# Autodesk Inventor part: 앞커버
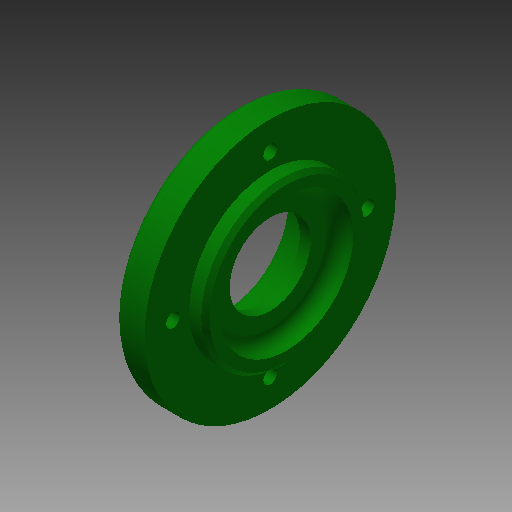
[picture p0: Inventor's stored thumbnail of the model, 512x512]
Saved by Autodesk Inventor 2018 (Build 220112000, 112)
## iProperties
Created: 2015-09
Part Number: 앞커버
Material: 알루미늄 6061
Document SubType Name: Modeling
Designer: mduedu
Density: 2.71 g/cm^3
Mass: 58.9874 g
Surface Area: 98.7754 cm^2
Volume: 21.7666 cm^3
Appearance: 진녹색
Author: mduedu
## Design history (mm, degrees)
sketch "스케치1"
  geometry: L1 (-8, 67)-(-12, 67); L2 (-12, 67)-(-12, 78); L3 (-12, 78)-(-20, 78); L4 (-20, 78)-(-20, 66); L5 (-23, 66)-(-23, 57); L6 (-23, 57)-(-8, 57); L7 (-8, 57)-(-8, 67); L8 (-79.5, 39.5)-(-79.5, 54.5) reference; L9 (48.5, 54.5)-(48.5, 39.5) reference; L10 (-79.5, 47)-(48.5, 47); L11 (-20, 66)-(-23, 66); 3 further points
  constraints: 18 end point, 6 parallel, 4 midpoint, 1 horizontal, 1 perpendicular, 1 vertical alignment
  dimensions: "d0" = 15 distance between parallel lines of L7 L5; "d2" = 20 diameter of L6 L10; "d3" = 40 diameter of L1 L10; "d5" = 4 distance of L1.start L1.end; "d6" = 62 diameter of L3 L10; "d7" = 8 distance of L2.end L3.end; "d8" = 38 diameter of L4.end L10
revolve "회전1" sketch "스케치1" stored, may be unused: angle "d4" = 90 deg
sketch "스케치2"
  geometry: C1 r 31 at (0, 0) reference; 2 further points
  constraints: 1 coincident
hole "구멍1" sketch "스케치2" at (0, 0) diameter "d11" = 33; stored, may be unused: countersink angle "d15" = 90 deg, drill point angle "d17" = 0 deg; dims "d12" = 6, "d13" = 4, "d14" = 2, "d16" = 4
fillet "모깎기1" dims "d18" = 3
fillet "모깎기2" dims "d19" = 1, "d60" = 3
sketch "스케치3"
  geometry: C1 r 31 at (0, 0) reference; 2 further points
  constraints: 1 coincident
hole "구멍2" sketch "스케치3" at (0, 0) diameter "d20" = 30; stored, may be unused: countersink angle "d24" = 90 deg, drill point angle "d26" = 0 deg; dims "d21" = 6, "d22" = 4, "d23" = 2, "d25" = 8.3
fillet "모깎기3" dims "d27" = 0.3
chamfer "모따기1" distance "d28" = 0.8; stored, may be unused: second distance "d29" = 2, angle "d30" = 30 deg
sketch "스케치4" dims "d31" = 56
  geometry: C1 r 31 at (0, 0) reference; 6 further points
  constraints: 2 vertical alignment, 1 coincident, 7 other
  dimensions: "d36" = 360 deg dimension on C1.centre point (0, 28) (derived)
sketch "스케치7"
  geometry: C1 r 30.5 at (0, 0) reference; A1 r 24 centre (0, 0) between (24, 0) and (0, 24); 2 further points
  constraints: 4 point on circle, 2 horizontal alignment, 2 vertical alignment, 1 centre point, 1 coincident
  dimensions: "d58" = 48 diameter of A1
hole "구멍4" sketch "스케치7" at (0, 24), (-24, 0), (24, 0), (0, -24) diameter "d48" = 3.4; stored, may be unused: countersink angle "d52" = 90 deg, drill point angle "d54" = 0 deg; dims "d49" = 6, "d50" = 6.5, "d51" = 3.4, "d53" = 8
chamfer "모따기2" distance "d55" = 1; stored, may be unused: second distance "d56" = 2, angle "d57" = 45 deg
node "솔리드1"
node "참조1"
node "참조2"
node "참조3"
